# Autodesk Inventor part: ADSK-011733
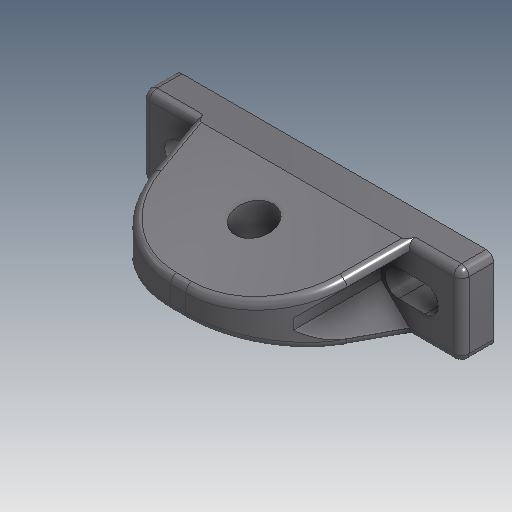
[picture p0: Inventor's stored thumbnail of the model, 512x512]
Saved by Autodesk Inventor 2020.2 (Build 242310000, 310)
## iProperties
Created: 1999-11
Part Number: ADSK-011733
Material: Acier doux
Description: PILLOW BLK BEARING
Document SubType Name: Modeling
Designer: cmcgourin
Density: 7.86 g/cm^3
Appearance: Metal-Steel(Polish)
Mass: 1060.73 g
Surface Area: 236.394 cm^2
Volume: 134.953 cm^3
Control State: 0
Checked Out: False
Last Check In By: sspink
Last Check In Date: 1999-12-16
Master: False
Shininess: 0.0
Length Units: 11272
Angle Units: 11279
Time Units: 11290
Mass Units: 11286
Length Display Precision: 3
Angle Display Precision: 2
Compacted: True
Dimensions: 1,4x2,6x5,3 in
Mass: 2,339 lb
VLT_Material: Acier doux
Density: 0.0
Volumn: 0.0
Area: 0.0
PropertySet Name: Model Information
Author: cmcgourin
Revision Number: -
Title: PILLOW BLK BEARING
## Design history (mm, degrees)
node "Base" dims "d24" = 13.49375, "d25" = 0
node "Slots" dims "d39" = 13.49375, "d40" = 0
node "Casting" dims "d43" = 51.59375, "d44" = -12 deg
node "Fillet1" dims "d45" = 38.1
workpoint "Work Point1"
workplane "Work Plane3"
workplane "Work Plane4"
workplane "Work Plane5"
node "shaft collar" dims "d52" = 51.59375, "d53" = 0
node "Bore" dims "d54" = 51.59375, "d55" = 0
node "Fillet3" dims "d56" = 3.175
node "Fillet4" dims "d57" = 3.175
node "Fillet5" dims "d58" = 3.175
node "Fillet6" dims "d59" = 3.175
node "Extrusion6" dims "d62" = 51.59375, "d63" = 0
workplane "Work Plane6"
node "Extrusion9" dims "d68" = 51.59375, "d69" = 0
workplane "Work Plane7"
workplane "Work Plane8"
workaxis "Work Axis2"
workaxis "Work Axis3"
node "Solide1"
node "Corps solides"
node "Corps surfaciques"
sketch "Sketch1"
  geometry: L1 (-25.557, 0.012)-(101.443, 0.012); L2 (104.618, 3.187)-(104.618, 30.969); L3 (101.443, 34.144)-(-25.557, 34.144); L4 (-28.732, 30.969)-(-28.732, 3.187); L5 (-28.732, 17.078)-(104.618, 17.078); A1 r 3.175 centre (-25.557, 30.969) between (-25.557, 34.144) and (-28.732, 30.969); A2 r 3.175 centre (-25.557, 3.187) between (-28.732, 3.187) and (-25.557, 0.012); A3 r 3.175 centre (101.443, 3.187) between (101.443, 0.012) and (104.618, 3.187); A4 r 3.175 centre (101.443, 30.969) between (104.618, 30.969) and (101.443, 34.144); 3 further points
  constraints: 10 end point, 8 point on circle, 8 tangent, 6 point on line, 4 centre point, 2 midpoint, 2 perpendicular, 1 parallel, 1 vertical
  dimensions: "d0" = 34.13125 distance of point (-28.732, 34.144) point (-28.732, 0.012); "d1" = 133.35 distance of point (-28.732, 0.012) point (104.618, 0.012); "d20" = 3.175 radius of A1; "d21" = 3.175 radius of A2; "d22" = 3.175 radius of A3; "d23" = 3.175 radius of A4
sketch "Sketch2"
  geometry: L1 (104.618, 3.187)-(104.618, 30.969) reference; L2 (101.443, 34.144)-(-25.557, 34.144) reference; L3 (-28.732, 30.969)-(-28.732, 3.187) reference; L4 (-25.557, 0.012)-(101.443, 0.012) reference; L5 (-28.732, 17.078)-(104.618, 17.078); L6 (-13.651, 22.634)-(-2.538, 22.634); L7 (-2.538, 11.522)-(-13.651, 11.522); L8 (78.424, 22.634)-(89.442, 22.634); L9 (89.537, 22.634)-(89.537, 11.522); L10 (89.442, 11.522)-(78.424, 11.522); L11 (78.424, 11.522)-(78.424, 22.634); L12 (-25.4, 17.078)-(-12.7, 17.078); L13 (37.943, 34.144)-(37.943, 0.012); L14 (-2.538, 22.634)-(-2.538, 11.871); L15 (78.424, 11.522)-(78.424, 22.634); L16 (-13.651, 11.522)-(-13.651, 22.634); A1 r 5.556 centre (-13.651, 17.078) between (-13.651, 22.634) and (-13.651, 11.522); A2 r 5.557 centre (89.537, 17.078) between (89.442, 11.522) and (89.442, 22.634); A3 r 5.556 centre (78.424, 17.078) between (78.424, 22.634) and (78.424, 11.522); A4 r 5.556 centre (-2.538, 17.078) between (-2.538, 11.522) and (-2.538, 22.634)
  constraints: 24 end point, 8 point on circle, 7 midpoint, 5 parallel, 5 point on line, 4 centre point, 2 collinear, 2 horizontal, 2 perpendicular
  dimensions: "d34" = 40.48125 horizontal distance of L11.start L13.end; "d36" = 11.1125 distance of L9.start L11.end (= d38); "d70" = 5.55625 distance between parallel lines of L8 L5; "d71" = 5.55625 distance between parallel lines of L10 L5 (= d70); "d72" = 5.55625 distance between parallel lines of L6 L5 (= d70); "d73" = 5.55625 distance between parallel lines of L7 L5 (= d72); "d74" = 40.48125 distance between parallel lines of L14 L13; "d75" = 11.1125 distance between parallel lines of L16 L14
sketch "Sketch3"
  geometry: L1 (101.443, 34.144)-(-25.557, 34.144) reference; L2 (-25.557, 0.012)-(101.443, 0.012) reference; L3 (-7.019, 34.144)-(82.906, 34.144); L4 (82.906, 34.144)-(82.906, 0.012); L5 (82.906, 0.012)-(-7.019, 0.012); L6 (-7.019, 0.012)-(-7.019, 34.144)
  constraints: 8 end point, 2 parallel, 2 point on line, 1 horizontal, 1 perpendicular
sketch "Sketch4"
  geometry: L1 (87.194, 33.338)-(5.654, 33.338); L2 (3.175, 0)-(0, 0) reference; L3 (111.638, 13.494)-(21.712, 13.494) reference; L4 (0, 13.494)-(0, 0) reference; C1 r 12.319 at (66.675, 33.338); C2 r 7.938 at (66.675, 33.338)
  constraints: 2 centre point, 2 end point, 1 coincident, 1 horizontal, 1 point on line
  dimensions: "d48" = 33.3375 distance from line of L1.end L2; "d49" = 24.638 diameter of C1; "d50" = 15.875 diameter of C2; "d76" = 66.675 distance from line of C1.centre L4 (= 0.5 x d1)
sketch "Sketch5"
  geometry: C1 r 7.937 at (0, 0) reference
sketch "Sketch8"
  geometry: L1 (82.906, 30.969)-(82.906, 22.634) reference; L2 (82.906, 11.522)-(82.906, 3.187) reference; L3 (-7.019, 3.187)-(-7.019, 11.522) reference; L4 (82.906, 11.522)-(82.906, 22.634) reference; L5 (-7.019, 22.634)-(-7.019, 30.969) reference; L6 (82.906, 30.969)-(71.197, 19.26); L7 (71.197, 19.26)-(71.197, 14.896); L8 (71.197, 14.896)-(82.906, 3.187)
  constraints: 6 end point
sketch "Sketch9"
  geometry: L1 (-96.754, -16.073)-(-96.754, -11.708) reference; L2 (-96.754, -11.708)-(-103.911, -4.552) reference; L3 (-103.911, -23.229)-(-96.754, -16.073) reference; L4 (-18.537, -8.334)-(-18.537, 0) reference; L5 (-18.537, -27.781)-(-18.537, -19.447) reference; L6 (-18.537, 0)-(-30.246, -11.708); L7 (-30.246, -16.073)-(-18.537, -27.781); L8 (-30.246, -16.073)-(-30.246, -11.708); L9 (-18.537, -19.447)-(-18.537, -27.781); L10 (-18.537, -19.447)-(-18.537, 0); A1 r 5.207 centre (-9.62, -13.891) between (-9.62, -19.098) and (-9.62, -8.684) reference; 2 other entities
  constraints: 10 end point, 3 parallel, 1 collinear, 1 perpendicular, 1 point on line, 2 other
other parameters: "d38" = 11.1125, "d47" = -18.65312, "d51" = 8.33438
